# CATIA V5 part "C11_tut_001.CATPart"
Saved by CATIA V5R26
Part number: Part1
Bounding box of the stored display mesh (mm): x -74.368 to 0, y -50 to 50, z -100 to 0
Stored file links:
  D:\_Deepak\CATIA\CATIA V5 2015 Parts Files\Tutorial Files\Tutorials\c11_catia_v5_6r2015_tut\C11_tut_001.CATPart
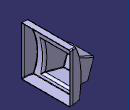
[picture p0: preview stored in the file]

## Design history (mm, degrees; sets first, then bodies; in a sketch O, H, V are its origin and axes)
Body1 (main body)
  Sketch1 on zx-plane, origin (0, 0, 0), H (-1, 0, 0), V (0, 0, 1)
    line L1 (0, 0) -> (12, 0)
    arc A1 centre (-96.8872, -61.3887) radius 125 from (12, 0) to (22, -100) cw
    line L2 (22, -100) -> (0, -100)
    point P4 (0, -100)
    length L1 = 12
    length L2 = 22
    distance L1 L2 = 100
    radius A1 = 125
    horizontal: L1 H, L2 H
    coincidence: P4 V
  Extrude1: Element1 Sketch1, Lim1 50, Lim2 50
  Sketch2 on zx-plane, origin (0, 0, 0), H (-1, 0, 0), V (0, 0, 1)
    line L1 (20, -40) -> (74.9495, -60)
    point P1 (20, -40)
    point P2 (74.9495, -60)
    reference projected line E1 (22, -100) -> (0, -100) from edge of Extrude1
    distance P2 H = 60
    distance P1 E1 = 60
    distance V P1 = 20
    angle L1 H = 20
  Plane1: type Normal, Curve Sketch2, RefPoint Sketch2.P2, Ratio 0
  Sketch3 on Plane1, origin (-85.4657, 0, -31.107), H (0, -1, 0), V (-0.342, 0, 0.9397)
    point P1 (-25, -30.7473)
    line L1 (-25, -30.7473) -> (25, -30.7473)
    line L2 (25, -30.7473) -> (25, -70.7473)
    line L3 (25, -70.7473) -> (-25, -70.7473)
    line L4 (-25, -70.7473) -> (-25, -30.7473)
    point P2 (25, -30.7473)
    reference projected point E1 (0, -30.7473) from Sketch2.P2
    axis line L5 (0, 21.6916) -> (0, -100.0328)
    point P5 (0, 21.6916)
    length L3 = 50
    length L2 = 40
    horizontal: L1 H, L3 H
    vertical: L2 V, L4 V, L5 V
    coincidence: L1 E1, P5 V
    symmetry: P1 P2 L5
  Plane2: type Normal, Curve Sketch2, RefPoint Sketch2.P1, Ratio 0
  Sketch4 on Plane2, origin (-30.5162, 0, -11.107), H (0, -1, 0), V (-0.342, 0, 0.9397)
    line L1 (-32.5, -21.2473) -> (32.5, -21.2473)
    line L2 (32.5, -21.2473) -> (32.5, -81.2473)
    line L3 (32.5, -81.2473) -> (-32.5, -81.2473)
    line L4 (-32.5, -81.2473) -> (-32.5, -21.2473)
    reference projected line E1 (25, -30.7473) -> (-25, -30.7473) from Sketch3.L1
    distance E1 L1 = 9.5
    distance V L2 = 32.5
    length L3 = 65
    length L2 = 60
    horizontal: L1 H, L3 H
    vertical: L2 V, L4 V
  Loft1: Sections (Sketch3; Sketch4), SectionCouplingPoints ({coupling CouplingPoints (vertex [element of Sketch3 | element of Sketch3]; vertex [element of Sketch4 | element of Sketch4])}; {coupling CouplingPoints (vertex [element of Sketch3 | element of Sketch3]; vertex [element of Sketch4 | element of Sketch4])}; {coupling CouplingPoints (vertex [element of Sketch3 | element of Sketch3]; vertex [element of Sketch4 | element of Sketch4])}; {coupling CouplingPoints (vertex [element of Sketch3 | element of Sketch3]; vertex [element of Sketch4 | element of Sketch4])})
  Sketch5 on face of Extrude1 from Sketch1.L1, origin (0, 0, 0), H (1, 0, 0), V (0, -1, 0)
    point P1 (0, -50)
    line L1 (0, -50) -> (-5, -50)
    reference projected point E1 (0, -50) from vertex [face of Extrude1 from Sketch1.L2]
    arc A1 centre (-5, 0) radius 50 from (-5, -50) to (-35.922, -39.2916) cw
    length L1 = 5
    radius A1 = 50
    horizontal: L1 H
    coincidence: P1 E1
    tangency: A1 L1
  Extrude2: Element1 Sketch5, Lim1 100, Lim2 0
  Symmetry1: ToTransfor Extrude2, Reference zx-plane
  Trim1: Trimmed (Extrude2; Extrude1)
  Trim2: Trimmed (Trim1; Symmetry1)
  Trim3: Trimmed (Loft1; Trim2)
  CloseSurface1: CloseElement Trim3
  Sketch6 on face of CloseSurface1, origin (-85.4657, 0, -31.107), H (0, -1, 0), V (-0.342, 0, 0.9397)
    line L1 (-20, -55.7473) -> (0, -55.7473)
    line L2 (0, -55.7473) -> (0, -65.7473)
    line L3 (0, -65.7473) -> (-20, -65.7473)
    line L4 (-20, -65.7473) -> (-20, -55.7473)
    reference projected line E1 (-25, -70.7473) -> (25, -70.7473) from edge [face of CloseSurface1 | face of CloseSurface1]
    reference projected line E2 (-25, -30.7473) -> (-25, -70.7473) from edge [face of CloseSurface1 | face of CloseSurface1]
    length L1 = 20
    length L4 = 10
    distance L3 E1 = 5
    distance L4 E2 = 5
    horizontal: L1 H, L3 H
    vertical: L2 V, L4 V
  Pocket1: profile Sketch6, direction (0.9397, 0, 0.342), length 5
  Fillet1: radius 1, on edge [face of CloseSurface1 | face of Pocket1 from Sketch6.L1]; edge [face of CloseSurface1 | face of Pocket1 from Sketch6.L2]; edge [face of CloseSurface1 | face of Pocket1 from Sketch6.L3]; edge [face of CloseSurface1 | face of Pocket1 from Sketch6.L4]; face of Pocket1 from Sketch6.L1; edge [face of Pocket1 from Sketch6.L1 | face of Pocket1 from Sketch6.L2]; edge [face of Pocket1 from Sketch6.L2 | end face of Pocket1]; edge [face of Pocket1 from Sketch6.L2 | face of Pocket1 from Sketch6.L3]; edge [face of Pocket1 from Sketch6.L3 | end face of Pocket1]; edge [face of Pocket1 from Sketch6.L3 | face of Pocket1 from Sketch6.L4]; edge [face of Pocket1 from Sketch6.L4 | end face of Pocket1]
  Fillet2: radius 3.5, on edge [face of CloseSurface1 | face of CloseSurface1] (x4)
  Fillet3: radius 2, on edge [face of CloseSurface1 | face of CloseSurface1] (x12)
  Fillet4: radius 2, on edge [face of CloseSurface1 | face of CloseSurface1] (x5); edge [face of CloseSurface1 | face of Fillet3]
  Shell1: ExtOffset 0, Face face of CloseSurface1, IntOffset 1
